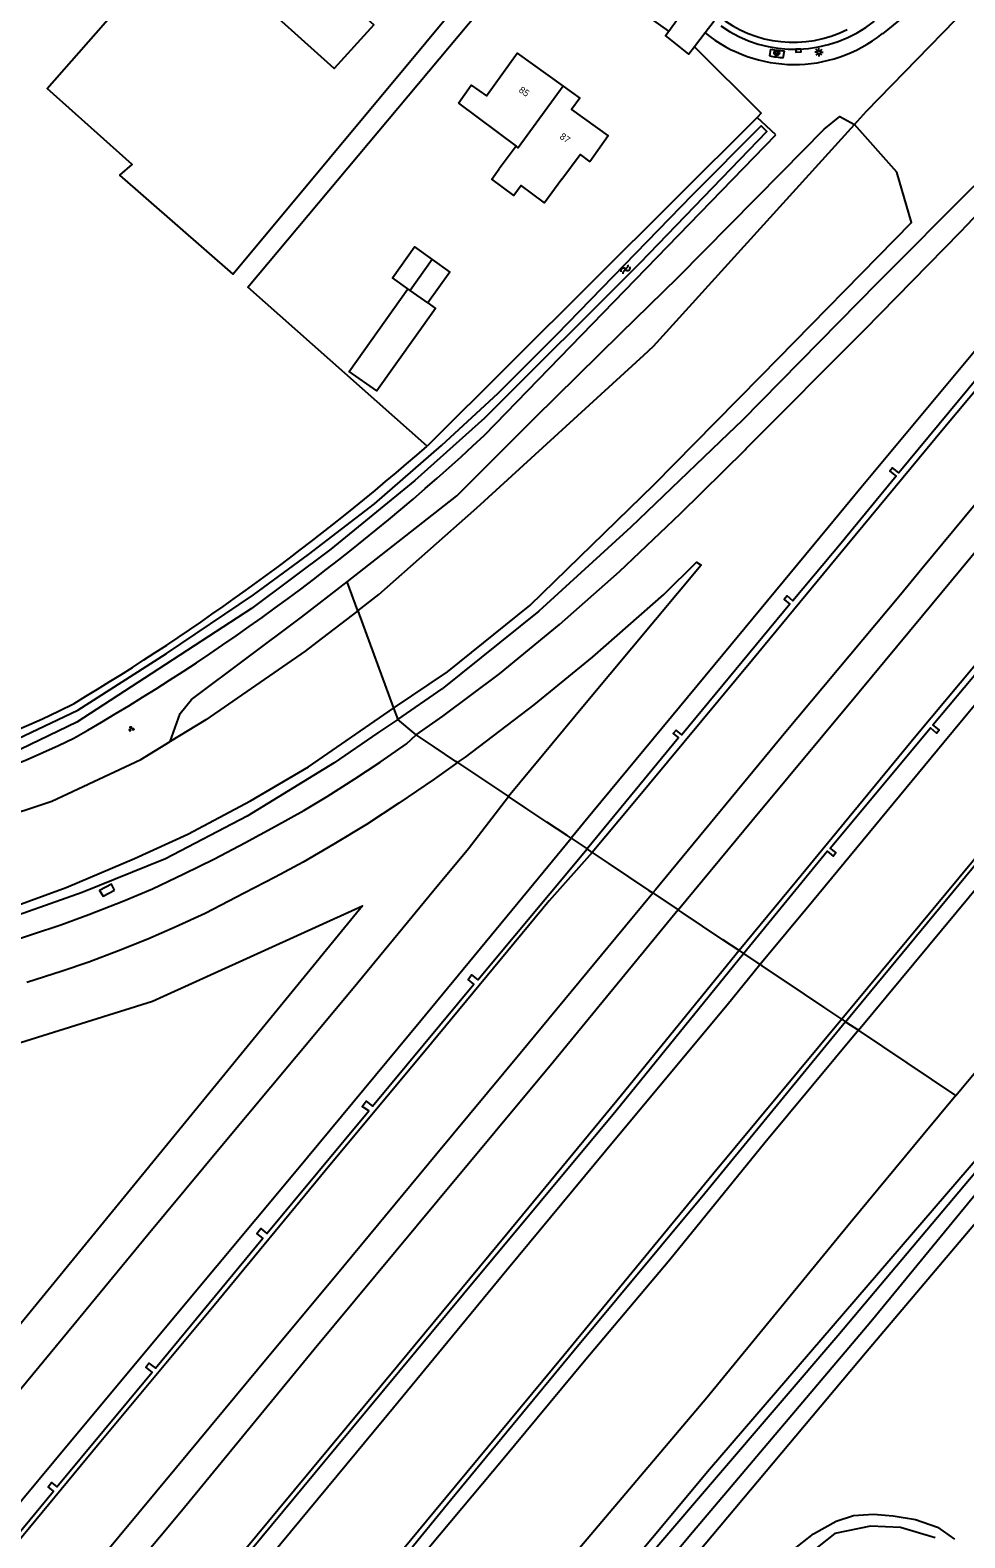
# Model space of a CAD drawing. Extents: x 135990 to 139000, y 393500 to 396000.
# Drawn here: x 136123.7 to 136262.1, y 395106.7 to 395330 of the extents above; entities that cross this region are included whole.
import ezdxf

# ---------------------------------------------------------------- set-up
doc = ezdxf.new("R2010")
doc.units = 0
for name, color, linetype in [('gg-afsc-erfafscheiding', 7, 'Continuous'), ('gg-afsc-hekwerk', 7, 'Continuous'), ('gg-anno-huisnummerreeks BGT', 7, 'Continuous'), ('gg-bbg-gedigitaliseerde bebouwing', 7, 'Continuous'), ('gg-bbg-gedigitaliseerde bijgebouw', 7, 'Continuous'), ('gg-bbg-hoofdgebouw', 7, 'Continuous'), ('gg-bbg-tussenscheiding', 7, 'Continuous'), ('gg-knt-BGT kruinlijn', 7, 'Continuous'), ('gg-knt-verharding', 7, 'Continuous'), ('gg-kntw-bovenkant insteek waterloop', 7, 'Continuous'), ('gg-kntw-waterlijn', 7, 'Continuous'), ('gt-grn-vlakafsluiter', 7, 'Continuous'), ('gt-grn-weggrens', 7, 'Continuous'), ('gt-symb-boom', 7, 'Continuous'), ('gt-symb-groenvak', 7, 'Continuous'), ('gt-symb-kolk', 7, 'Continuous'), ('gt-symb-lichtmast', 7, 'Continuous'), ('gt-symb-watersymbool', 7, 'Continuous'), ('gx-grn-maaiveld', 7, 'Continuous')]:
    doc.layers.add(name, color=color, linetype=linetype)

# ---------------------------------------------------------------- blocks, each defined once
blk = doc.blocks.new('gt0-BOOM')
at = {"layer": 'gt-symb-boom'}
for radius in [0.4, 0.2]:
    blk.add_circle((0, 0), radius, dxfattribs=at)
blk = doc.blocks.new('gt0-LMAST')
at = {"layer": 'gt-symb-lichtmast'}
for p, q in [((-0.18, 0.17), (-0.45, 0.44)), ((-0.01, 0.25), (-0.01, 0.62)), ((0.17, 0.17), (0.44, 0.44)), ((-0.26, 0), (-0.63, 0)), ((-0.18, -0.18), (-0.45, -0.45)), ((-0.01, -0.25), (-0.01, -0.63)), ((0.44, -0.45), (0.17, -0.18)), ((0.24, 0), (0.62, 0))]:
    blk.add_line(p, q, dxfattribs=at)
blk.add_circle((-0.01, 0), 0.25, dxfattribs=at)
blk = doc.blocks.new('gt0-KOLK')
at = {"layer": 'gt-symb-kolk'}
blk.add_lwpolyline([(0, 0), (0.38, 0), (0.38, 0.4), (-0.38, 0.4), (-0.38, 0), (0, 0)], dxfattribs=at)
blk = doc.blocks.new('gt0-WA')
at = {"layer": 'gt-symb-watersymbool'}
for centre, start, end in [((-0.32, 0.02), 28.0725, 151.9275), ((0.43, 0.42), 208.0725, 331.9275), ((-0.32, -0.43), 28.0725, 151.9275), ((0.43, -0.03), 208.0725, 331.9275)]:
    blk.add_arc(centre, 0.425, start, end, dxfattribs=at)
blk = doc.blocks.new('gt0-GRVAK')
at = {"layer": 'gt-symb-groenvak'}
for p, q in [((-0.11, 0.19), (-0.23, 0.24)), ((-0.18, 0.15), (0.09, 0.15)), ((-0.09, 0.21), (-0.16, 0.32)), ((-0.05, 0.21), (-0.05, 0.39)), ((0, 0.21), (0.06, 0.32)), ((0.01, 0.19), (0.13, 0.24)), ((0.26, -0.05), (0.2, 0.06)), ((0.3, -0.05), (0.3, 0.13)), ((0.35, -0.05), (0.41, 0.06)), ((-0.25, -0.23), (-0.36, -0.18)), ((-0.32, -0.26), (-0.05, -0.26)), ((-0.23, -0.21), (-0.29, -0.09)), ((-0.18, -0.2), (-0.18, -0.02)), ((-0.14, -0.21), (-0.07, -0.09)), ((-0.12, -0.23), (0, -0.18)), ((0.24, -0.07), (0.12, -0.02)), ((0.17, -0.11), (0.44, -0.11)), ((0.37, -0.07), (0.49, -0.02))]:
    blk.add_line(p, q, dxfattribs=at)

msp = doc.modelspace()

# ---------------------------------------------------------------- linework, layer by layer
at = {"layer": 'gg-afsc-erfafscheiding'}
msp.add_line((136218.27, 395329.906), (136204.457, 395339.72), dxfattribs=at)
at = {"layer": 'gg-afsc-hekwerk'}
msp.add_lwpolyline([(136222.071, 395327.588), (136231.963, 395317.741), (136231.371, 395317.103)], dxfattribs=at)
msp.add_lwpolyline([(136222.071, 395327.588), (136231.963, 395317.741), (136231.371, 395317.103)], dxfattribs=at)
at = {"layer": 'gg-bbg-gedigitaliseerde bebouwing'}
for p, q in [((136187.111, 395319.21), (136195.653, 395312.861)), ((136195.653, 395312.861), (136193.163, 395309.5))]:
    msp.add_line(p, q, dxfattribs=at)
for points in [[(136202.429, 395307.952), (136205.131, 395311.599), (136206.561, 395310.54)], [(136202.429, 395307.952), (136199.873, 395304.48), (136196.398, 395307.037), (136195.31, 395305.559), (136192.036, 395307.969), (136193.163, 395309.5)]]:
    msp.add_lwpolyline(points, dxfattribs=at)
at = {"layer": 'gg-bbg-gedigitaliseerde bijgebouw'}
for points in [[(136179.641, 395291.726), (136177.343, 395293.36), (136180.6, 395297.939), (136183.219, 395296.077)], [(136183.219, 395296.077), (136185.838, 395294.215), (136182.581, 395289.636)], [(136182.581, 395289.636), (136183.716, 395288.828), (136175.023, 395276.604), (136170.948, 395279.502), (136179.641, 395291.726)]]:
    msp.add_lwpolyline(points, dxfattribs=at)
at = {"layer": 'gg-bbg-hoofdgebouw'}
for points in [[(136155.641, 395336.16), (136161.521, 395342.62), (136174.571, 395330.83), (136168.711, 395324.35), (136155.641, 395336.16)], [(136187.111, 395319.21), (136189.001, 395321.9), (136191.251, 395320.32), (136195.791, 395326.63), (136202.602, 395321.757)], [(136202.602, 395321.757), (136205.071, 395319.99), (136203.871, 395318.29), (136209.311, 395314.38), (136206.561, 395310.54)]]:
    msp.add_lwpolyline(points, dxfattribs=at)
at = {"layer": 'gg-bbg-tussenscheiding'}
for p, q in [((136183.219, 395296.077), (136179.962, 395291.498)), ((136179.962, 395291.498), (136179.641, 395291.726)), ((136182.581, 395289.636), (136179.962, 395291.498))]:
    msp.add_line(p, q, dxfattribs=at)
msp.add_lwpolyline([(136202.602, 395321.757), (136195.983, 395312.608), (136195.653, 395312.861)], dxfattribs=at)
at = {"layer": 'gg-knt-BGT kruinlijn'}
for p, q in [((136263.44, 395306.94), (136249.21, 395292.636)), ((136249.21, 395292.636), (136229.109, 395272.184)), ((136227.063, 395270.225), (136212.635, 395256.407)), ((136229.109, 395272.184), (136227.063, 395270.225)), ((136212.635, 395256.407), (136199.006, 395243.964)), ((136199.006, 395243.964), (136184.712, 395232.461)), ((136178.122, 395227.952), (136184.712, 395232.461)), ((136178.122, 395227.952), (136175.172, 395225.934)), ((136175.172, 395225.934), (136168.71, 395221.512)), ((136168.71, 395221.512), (136155.841, 395213.599)), ((136155.841, 395213.599), (136143.703, 395207.303)), ((136143.703, 395207.303), (136131.373, 395202.288)), ((136246.364, 395181.897), (136264.959, 395204.263)), ((136131.373, 395202.288), (136117.643, 395197.487)), ((136246.364, 395181.897), (136232.517, 395165.247)), ((136232.517, 395165.247), (136218.434, 395147.902)), ((136218.434, 395147.902), (136205.747, 395132.857)), ((136205.747, 395132.857), (136193.721, 395118.35)), ((136193.721, 395118.35), (136179.401, 395101.269))]:
    msp.add_line(p, q, dxfattribs=at)
at = {"layer": 'gg-knt-verharding'}
for p, q in [((136289.468, 395361.63), (136249.912, 395329.52)), ((136223.641, 395329.661), (136222.071, 395327.588)), ((136233.361, 395327.228), (136233.19, 395326.217)), ((136235.212, 395325.959), (136235.405, 395326.978))]:
    msp.add_line(p, q, dxfattribs=at)
for points in [[(136218.27, 395329.906), (136219.645, 395331.815), (136205.978, 395341.838), (136204.457, 395339.72)], [(136222.071, 395327.588), (136221.244, 395326.496), (136217.792, 395329.242), (136218.27, 395329.906)]]:
    msp.add_lwpolyline(points, dxfattribs=at)
for centre, radius, start, end in [((136236.712, 395345.862), 17.62, 231.01198, 296.87702), ((136236.884, 395346.115), 18.908, 234.73328, 308.8379), ((136236.864, 395345.866), 20.915, 230.78574, 308.59923), ((136237.411, 395351.244), 25.38, 260.42712, 265.02999), ((136235.687, 395337.763), 10.788, 257.55031, 268.50336)]:
    msp.add_arc(centre, radius, start, end, dxfattribs=at)
at = {"layer": 'gg-kntw-bovenkant insteek waterloop'}
for p, q in [((136231.371, 395317.103), (136182.483, 395268.442)), ((136234.123, 395314.55), (136231.371, 395317.103)), ((136190.994, 395270.058), (136234.123, 395314.55))]:
    msp.add_line(p, q, dxfattribs=at)
for centre, radius, start, end in [((135966.352, 395510.704), 329.203, 299.83989, 313.03007), ((135944.027, 395540.559), 361.813, 300.968, 311.22815), ((136053.157, 395384.301), 172.18, 268.89615, 296.581), ((136054.026, 395384.555), 176.654, 269.32985, 295.52815)]:
    msp.add_arc(centre, radius, start, end, dxfattribs=at)
at = {"layer": 'gg-kntw-waterlijn'}
msp.add_lwpolyline([(136120.838, 395224.644), (136130.744, 395229.304), (136143.882, 395237.726), (136156.777, 395246.419), (136164.887, 395252.395), (136174.668, 395259.896), (136184.622, 395268.501), (136193.011, 395276.248), (136201.711, 395284.966), (136221.779, 395305.655), (136231.951, 395315.879), (136232.791, 395315.044), (136213.969, 395295.545), (136190.967, 395272.554), (136180.636, 395263.312), (136168.215, 395253.158), (136156.455, 395244.393), (136141.606, 395234.712), (136130.609, 395227.543), (136122.298, 395223.551)], dxfattribs=at)
at = {"layer": 'gt-grn-vlakafsluiter'}
for points in [[(136196.555, 395345.334), (136153.746, 395293.901), (136136.965, 395308.571), (136138.775, 395310.131), (136126.192, 395321.407), (136139.516, 395336.608), (136134.358, 395341.535), (136160.697, 395370.426)], [(136182.483, 395268.442), (136155.918, 395291.987), (136199.089, 395343.534)]]:
    msp.add_lwpolyline(points, dxfattribs=at)
at = {"layer": 'gt-grn-weggrens'}
msp.add_line((136225.001, 395331.385), (136223.641, 395329.661), dxfattribs=at)
at = {"layer": 'gx-grn-maaiveld'}
for p, q in [((136172.189, 395244.038), (136170.616, 395248.304)), ((136172.189, 395244.038), (136177.507, 395229.62)), ((136177.507, 395229.62), (136178.122, 395227.952)), ((136180.83, 395225.678), (136178.122, 395227.952)), ((136186.993, 395221.56), (136194.537, 395216.52)), ((136203.801, 395210.332), (136206.166, 395208.752)), ((136206.942, 395208.234), (136206.166, 395208.752)), ((136215.892, 395202.254), (136219.646, 395199.746)), ((136228.684, 395193.708), (136229.359, 395193.257)), ((136229.359, 395193.257), (136231.776, 395191.643)), ((136243.91, 395183.536), (136244.461, 395183.168)), ((136244.461, 395183.168), (136246.364, 395181.897)), ((136260.813, 395172.244), (136246.364, 395181.897))]:
    msp.add_line(p, q, dxfattribs=at)
for points in [[(136245.799, 395316.07), (136247.57, 395318.024), (136268.264, 395339.315), (136278.485, 395349.281), (136284.643, 395355.052), (136289.897, 395358.868), (136293.095, 395360.152), (136296.843, 395360.229), (136301.25, 395358.764), (136304.764, 395356.245)], [(136180.83, 395225.678), (136184.812, 395228.425), (136193.216, 395234.685), (136202.066, 395242), (136210.951, 395249.879), (136220.014, 395258.455), (136229.572, 395267.884), (136229.758, 395268.067), (136247.241, 395285.658), (136261.458, 395300.179), (136266.233, 395305.147), (136269.32, 395308.628), (136277.453, 395318.127), (136294.031, 395338.167), (136296.887, 395341.848), (136298.245, 395344.401), (136300.943, 395347.74)], [(136306.163, 395333.393), (136292.816, 395317.473), (136274.414, 395295.48), (136246.779, 395262.308), (136241.892, 395256.389), (136226.301, 395237.504), (136207.038, 395214.234), (136203.801, 395210.332)], [(136306.858, 395330.088), (136291.372, 395311.273), (136290.335, 395312.14), (136289.89, 395311.607), (136290.869, 395310.788), (136270.503, 395286.431), (136269.448, 395287.303), (136268.936, 395286.685), (136270.011, 395285.796), (136252.366, 395264.45), (136251.422, 395265.224), (136251.021, 395264.735), (136251.957, 395263.966), (136244.469, 395254.834), (136244.069, 395254.357), (136236.663, 395245.523), (136235.801, 395246.235), (136235.382, 395245.728), (136236.217, 395245.038), (136220.224, 395225.664), (136219.368, 395226.37), (136218.934, 395225.844), (136219.719, 395225.197), (136206.166, 395208.752)], [(136307.655, 395329.293), (136285.512, 395302.725), (136258.897, 395270.943), (136244.705, 395253.764), (136230.657, 395236.759), (136212.985, 395215.487), (136206.942, 395208.234)], [(136170.616, 395248.304), (136186.866, 395261.077), (136198.431, 395272.635), (136211.127, 395285.094), (136219.662, 395293.47), (136235.016, 395309.025), (136241.294, 395315.384), (136243.585, 395317.23), (136245.799, 395316.07)], [(136311.839, 395317.793), (136287.338, 395288.371), (136255.745, 395250.232), (136252.572, 395246.424), (136235.631, 395226.088), (136216.279, 395202.72), (136215.892, 395202.254)], [(136172.189, 395244.038), (136175.313, 395246.439), (136189.838, 395259.263), (136214.565, 395281.885), (136216.024, 395283.22), (136245.799, 395316.07)], [(136177.507, 395229.62), (136185.517, 395235.012), (136197.668, 395244.795), (136216.085, 395262.754), (136225.196, 395271.967), (136231.98, 395278.827), (136254.24, 395301.573), (136252.04, 395309.01), (136245.799, 395316.07)], [(136219.646, 395199.746), (136230.594, 395212.937), (136246.466, 395232.05), (136255.861, 395243.355), (136263.021, 395251.972), (136285.356, 395278.926), (136313.553, 395313.084)], [(136317.792, 395301.431), (136296.471, 395275.558), (136272.421, 395246.526), (136263.687, 395236.053), (136254.85, 395225.457), (136237.195, 395203.993), (136228.684, 395193.708)], [(136229.359, 395193.257), (136241.725, 395208.431), (136242.608, 395207.712), (136243.013, 395208.209), (136242.172, 395208.894), (136257.02, 395226.682), (136257.924, 395225.926), (136258.301, 395226.379), (136257.375, 395227.151), (136264.33, 395235.454), (136273.406, 395246.289), (136274.316, 395245.53), (136274.683, 395245.97), (136273.794, 395246.711), (136289.095, 395265.107), (136289.994, 395264.41), (136290.424, 395264.966), (136289.544, 395265.647), (136291.432, 395267.917), (136316.558, 395298.435), (136317.838, 395299.883)], [(136231.776, 395191.643), (136239.572, 395201.029), (136259.033, 395224.573), (136266.432, 395233.492), (136279.261, 395248.955), (136298.906, 395272.436), (136319.385, 395297.049)], [(136324.423, 395283.208), (136319.933, 395277.921), (136313.722, 395270.082), (136295.006, 395245.573), (136288.846, 395237.692), (136274.698, 395220.655), (136243.91, 395183.536)], [(136260.813, 395172.244), (136265.988, 395178.478), (136288.51, 395205.912), (136297.964, 395218.042), (136309.605, 395233.21), (136320.575, 395248.919), (136325.21, 395258.664), (136329.259, 395267.574), (136329.925, 395270.014), (136330.612, 395271.954), (136331.48, 395274.92), (136331.663, 395278.364), (136331.519, 395280.16), (136331.283, 395282.01)], [(136186.993, 395221.56), (136188.144, 395222.347), (136198.342, 395230.117), (136206.95, 395237.159), (136217.558, 395246.469), (136222.379, 395251.25), (136223.085, 395250.809), (136206.047, 395230.389), (136194.537, 395216.52)], [(136144.424, 395224.668), (136145.911, 395228.828), (136147.586, 395230.906), (136163.875, 395243.11), (136170.616, 395248.304)], [(136172.189, 395244.038), (136166.125, 395239.377), (136164.414, 395238.062), (136149.7, 395227.872), (136144.424, 395224.668)], [(136244.461, 395183.168), (136248.155, 395187.644), (136265.052, 395208.081), (136277.57, 395223.1), (136281.511, 395227.828), (136286.434, 395233.832), (136288.287, 395232.312)], [(136000, 395196.665), (136003.665, 395196.386), (136011.256, 395196.065), (136020.386, 395195.247), (136031.829, 395193.512), (136037.839, 395192.846), (136046.205, 395191.851), (136052.604, 395191.018), (136058.513, 395190.927), (136067.037, 395191.116), (136074.049, 395191.514), (136081.454, 395191.929), (136087.305, 395192.432), (136092.94, 395193.204), (136100.644, 395194.874), (136108.143, 395196.683), (136120.209, 395199.861), (136129.005, 395203.051), (136139.128, 395207.348), (136147.019, 395210.956), (136156.288, 395215.901), (136164.904, 395220.907), (136177.507, 395229.62)], [(136119.04, 395194.499), (136124.001, 395196.149), (136128.231, 395197.496), (136132.371, 395199.037), (136137.534, 395201.06), (136141.783, 395202.848), (136146.452, 395205.076), (136150.985, 395207.314), (136155.496, 395209.669), (136160.009, 395212.118), (136164.223, 395214.432), (136167.686, 395216.541), (136171.746, 395219.123), (136175.517, 395221.638), (136179.411, 395224.305), (136180.83, 395225.678)], [(136186.993, 395221.56), (136186.735, 395221.733), (136183.533, 395223.872), (136180.83, 395225.678)], [(136000, 395206.689), (136003.64, 395206.608), (136022.625, 395205.449), (136042.185, 395203.278), (136077.247, 395203.016), (136091.428, 395205.207), (136109.979, 395210.277), (136126.882, 395215.828), (136140.053, 395222.014), (136144.424, 395224.668)], [(136321.094, 395222.49), (136272.146, 395163.29), (136247.407, 395134.053), (136134.88, 395000), (136122.568, 394985.269), (136102.637, 394961.643), (136084.346, 394939.307), (136069.515, 394921.566), (136049.967, 394898.321), (136037.521, 394883.604)], [(136039.534, 394893.887), (136053.898, 394911.377), (136069.458, 394929.631), (136089.666, 394953.784), (136106.496, 394973.352), (136110.031, 394978.201), (136182.097, 395066.305), (136224.325, 395116.901), (136264.282, 395163.345), (136297.688, 395204.145), (136312.144, 395222.007)], [(136186.993, 395221.56), (136183.517, 395219.104), (136178.278, 395215.522), (136173.487, 395212.394), (136168.66, 395209.46), (136164.133, 395206.818), (136159.97, 395204.583), (136155.394, 395202.192), (136149.576, 395199.205), (136145.155, 395197.17), (136141.082, 395195.414), (136136.78, 395193.69), (136132.372, 395191.979), (136128.42, 395190.667), (136123.171, 395188.969)], [(136035.476, 394886.78), (136038.919, 394890.545), (136046.257, 394899.342), (136056.342, 394911.722), (136074.99, 394933.782), (136132.669, 395005.25), (136169.383, 395049.683), (136198.249, 395084.062), (136243.331, 395136.669), (136291.785, 395194.27), (136313.523, 395220.89)], [(136315.534, 395219.263), (136305.303, 395206.668), (136289.377, 395187.885), (136268.871, 395163.914), (136248.183, 395138.737), (136221.773, 395107.523), (136189.048, 395068.386), (136158.453, 395031.719), (136127.941, 394994.61), (136109.151, 394971.997), (136097.001, 394958.021), (136088.046, 394946.566), (136070.362, 394924.959), (136048.627, 394899.765), (136038.451, 394887.29), (136036.414, 394885.271)], [(136120.566, 395126.712), (136130.132, 395138.31), (136141.157, 395151.682), (136152.068, 395164.842), (136163.061, 395177.997), (136171.501, 395188.115), (136183.486, 395202.675), (136188.602, 395208.828), (136194.537, 395216.52)], [(136203.801, 395210.332), (136203.208, 395210.728), (136200.215, 395212.727), (136197.109, 395214.802), (136194.537, 395216.52)], [(136060.051, 395037.16), (136076.645, 395057.167), (136096.433, 395080.931), (136113.377, 395101.433), (136127.165, 395118.012), (136145.386, 395139.884), (136163.077, 395161.104), (136181.547, 395183.362), (136198.295, 395203.635), (136203.801, 395210.332)], [(136206.942, 395208.234), (136200.562, 395201.084), (136183.123, 395180.005), (136167.395, 395161.103), (136150.948, 395141.136), (136133.893, 395120.71), (136116.019, 395099.133), (136097.354, 395076.625), (136076.148, 395051.091), (136062.406, 395034.463)], [(136112.127, 395095.492), (136127.108, 395113.617), (136126.331, 395114.277), (136126.815, 395114.916), (136127.646, 395114.263), (136141.755, 395131.249), (136140.811, 395131.979), (136141.262, 395132.605), (136142.244, 395131.846), (136158.154, 395151.101), (136157.249, 395151.812), (136157.827, 395152.526), (136158.754, 395151.81), (136173.827, 395169.947), (136172.863, 395170.631), (136173.452, 395171.397), (136174.395, 395170.646), (136189.405, 395188.736), (136188.531, 395189.422), (136189.035, 395190.097), (136189.993, 395189.353), (136206.166, 395208.752)], [(136206.942, 395208.234), (136209.284, 395206.669), (136212.302, 395204.652), (136215.33, 395202.629), (136215.892, 395202.254)], [(136136.162, 395202.639), (136135.703, 395203.55), (136133.963, 395202.593), (136134.507, 395201.744), (136136.162, 395202.639)], [(136069.913, 395026.031), (136084.667, 395044.019), (136102.696, 395065.699), (136117.148, 395083.152), (136131.268, 395100.239), (136145.333, 395117.175), (136157.332, 395131.631), (136170.13, 395146.987), (136183.913, 395163.653), (136196.255, 395178.491), (136210.432, 395195.664), (136215.892, 395202.254)], [(136219.646, 395199.746), (136201.132, 395177.183), (136183.983, 395156.524), (136165.726, 395134.622), (136146.068, 395110.68), (136126.3, 395086.996), (136108.273, 395065.137), (136087.784, 395040.42), (136073.266, 395022.901)], [(136092.392, 395174.837), (136117.303, 395178.556), (136141.793, 395186.235), (136172.923, 395200.348), (136097.016, 395107.59)], [(136228.684, 395193.708), (136226.27, 395195.321), (136223.273, 395197.323), (136220.263, 395199.334), (136219.646, 395199.746)], [(136228.684, 395193.708), (136211.275, 395172.274), (136194.257, 395151.708), (136178.062, 395132.17), (136160.421, 395110.847), (136143.663, 395090.695), (136125.526, 395068.831), (136109.226, 395049.121), (136094.161, 395030.91), (136081.449, 395015.64)], [(136081.949, 395015.055), (136097.511, 395033.711), (136117.623, 395057.826), (136134.304, 395078.218), (136153.177, 395101.07), (136168.982, 395120.153), (136187.846, 395142.848), (136210.46, 395169.996), (136229.359, 395193.257)], [(136084.047, 395013.409), (136098.901, 395031.272), (136111.877, 395046.795), (136127.461, 395065.542), (136140.926, 395081.834), (136159.395, 395104.173), (136177.49, 395126.05), (136194.301, 395146.424), (136210.552, 395166.063), (136226.909, 395185.677), (136231.776, 395191.643)], [(136243.91, 395183.536), (136241.373, 395185.231), (136238.364, 395187.241), (136232.088, 395191.434), (136231.776, 395191.643)], [(136243.91, 395183.536), (136224.96, 395160.755), (136202.724, 395133.726), (136183.585, 395110.624), (136154.893, 395075.957), (136126.181, 395041.356), (136095.064, 395003.703)], [(136244.461, 395183.168), (136223.616, 395157.711), (136204.241, 395134.445), (136185.941, 395112.26), (136166.168, 395088.04), (136153.317, 395072.665), (136135.811, 395051.716), (136120.319, 395033.011), (136103.381, 395012.579), (136095.595, 395003.146)], [(136260.813, 395172.244), (136255.971, 395166.413), (136245.218, 395153.46), (136223.92, 395127.466), (136201.544, 395101.061), (136178.81, 395074.393), (136157.717, 395048.771), (136136.065, 395021.821), (136113.42, 394994.267), (136111.02, 394991.445)], [(136234.811, 395103.44), (136239.71, 395107.32), (136243.074, 395109.204), (136245.627, 395110.015), (136248.572, 395110.226), (136251.525, 395109.964), (136254.793, 395109.426), (136258.098, 395108.287), (136260.604, 395106.536)], [(136257.745, 395106.717), (136252.602, 395108.259), (136248.127, 395108.433), (136242.855, 395107.339), (136239.061, 395104.363)]]:
    msp.add_lwpolyline(points, dxfattribs=at)

# ---------------------------------------------------------------- block references
at = {"layer": 'gt-symb-boom'}
msp.add_blockref('gt0-BOOM', (136234.258, 395326.682), dxfattribs=at)
at = {"layer": 'gt-symb-groenvak'}
msp.add_blockref('gt0-GRVAK', (136138.636, 395226.56), dxfattribs=at)
at = {"layer": 'gt-symb-kolk', "rotation": -178.22439947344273}
msp.add_blockref('gt0-KOLK', (136237.473, 395327.216), dxfattribs=at)
at = {"layer": 'gt-symb-lichtmast'}
msp.add_blockref('gt0-LMAST', (136240.519, 395326.764), dxfattribs=at)
at = {"layer": 'gt-symb-watersymbool', "rotation": 44.83791901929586}
msp.add_blockref('gt0-WA', (136211.813, 395294.577), dxfattribs=at)

# ---------------------------------------------------------------- texts
at = {"layer": 'gg-anno-huisnummerreeks BGT'}
for s, rotation, p in [('85', 324.4, (136195.96, 395320.975)), ('87', 324.3, (136202.013, 395314.083))]:
    msp.add_text(s, height=1, rotation=rotation, dxfattribs=at).set_placement(p)

doc.saveas('drawing.dxf')
